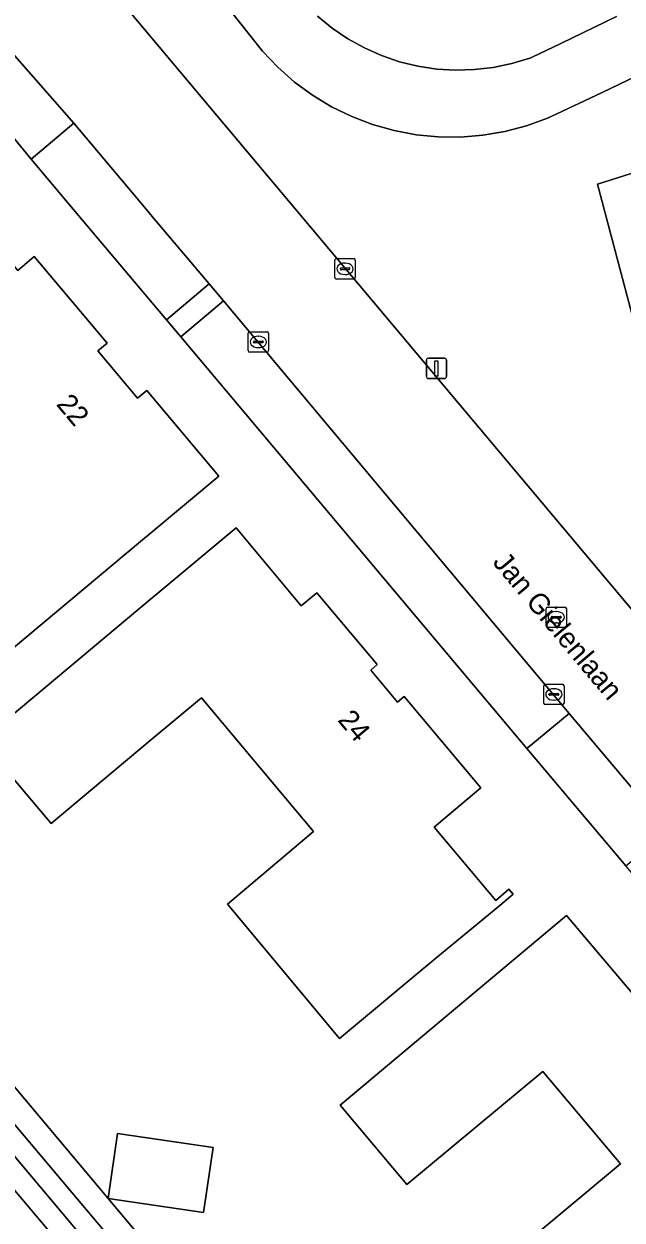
# Model space of a CAD drawing. Extents: x 157320 to 158835, y 386650 to 388491.
# Drawn here: x 157993.7 to 158023.1, y 386950.3 to 387009.1 of the extents above; entities that cross this region are included whole.
import ezdxf

# ---------------------------------------------------------------- set-up
doc = ezdxf.new("R2010")
doc.units = 0
for name, color, linetype in [('IMGEO_Erf', 7, 'Continuous'), ('IMGEO_Fietspad_gesloten', 7, 'Continuous'), ('IMGEO_Groenvoorziening', 7, 'Continuous'), ('IMGEO_Kolk', 7, 'Continuous'), ('IMGEO_Lichtmast', 7, 'Continuous'), ('IMGEO_Oever', 7, 'Continuous'), ('IMGEO_Openbare_ruimte_label', 7, 'Continuous'), ('IMGEO_Pand', 7, 'Continuous'), ('IMGEO_Pand_nummerreeks', 7, 'Continuous'), ('IMGEO_Rijbaan_lokaal_gesloten', 7, 'Continuous'), ('IMGEO_Rioolput', 7, 'Continuous'), ('IMGEO_Voetpad_gesloten', 7, 'Continuous'), ('IMGEO_Voetpad_open', 7, 'Continuous'), ('IMGEO_Waterloop', 7, 'Continuous')]:
    doc.layers.add(name, color=color, linetype=linetype)

msp = doc.modelspace()

# ---------------------------------------------------------------- linework, layer by layer
at = {"layer": 'IMGEO_Erf'}
for points in [[(158061.764, 386921.937), (158049.754, 386936.46), (158049.074, 386937.309), (158043.836, 386943.4), (158043.806, 386943.933), (158041.197, 386947.04), (158040.654, 386947.173), (158036.643, 386951.87), (158036.592, 386951.93), (158036.351, 386951.727), (158033.168, 386955.508), (158033.423, 386955.739), (158033.372, 386955.799), (158023.244, 386967.75), (158018.379, 386973.505), (158001.394, 386993.731), (158000.702, 386994.555), (157996.119, 387000), (157994.061, 387002.445), (157991.12, 387006.005), (157981.864, 387017.312)], [(157951.635, 387006.472), (157997.832, 386951.408), (158016.34, 386929.351), (158048.856, 386891.347)], [(157990.995, 386999.823), (157993.395, 386996.984), (157994.208, 386997.671), (157997.781, 386993.415), (157997.322, 386993.03), (157999.27, 386990.709), (157999.729, 386991.094), (158000, 386990.771), (158003.264, 386986.881), (158000, 386984.153), (157999.428, 386983.675), (157989.657, 386975.511), (157984.94, 386981.114), (157989.74, 386985.139), (157988.369, 386986.825)], [(157992.925, 386974.986), (158000, 386980.903), (158000.279, 386981.136), (158004.114, 386984.343), (158007.316, 386980.509), (158008.084, 386981.151), (158011.045, 386977.626), (158010.724, 386977.356), (158012.042, 386975.786), (158012.363, 386976.056), (158016.124, 386971.575), (158014.48, 386970.19), (158013.83, 386969.643), (158016.858, 386966.049), (158017.508, 386966.596), (158017.714, 386966.351), (158017.064, 386965.804), (158013.926, 386963.212), (158009.198, 386959.269), (158003.685, 386965.861), (158007.917, 386969.425), (158002.409, 386976), (158000, 386973.982), (157996.362, 386970.934), (157995.044, 386969.83), (157991.606, 386973.883)]]:
    msp.add_lwpolyline(points, dxfattribs=at)
for points in [[(158016.504, 386962.101), (158020.335, 386965.313), (158024.467, 386960.406), (158025.064, 386960.909), (158028.925, 386956.316), (158028.489, 386955.95), (158029.563, 386954.671), (158029.999, 386955.037), (158030.996, 386953.85), (158028.685, 386951.9), (158031.502, 386948.56), (158027.669, 386945.35), (158021.051, 386939.806), (158015.277, 386946.677), (158022.978, 386953.106), (158019.17, 386957.649), (158012.501, 386952.091), (158009.217, 386955.992)], [(157997.832, 386951.408), (157998.299, 386954.602), (158002.985, 386953.918), (158002.518, 386950.723)]]:
    msp.add_lwpolyline(points, close=True, dxfattribs=at)
at = {"layer": 'IMGEO_Fietspad_gesloten'}
for points in [[(158000, 387014.593), (158004.726, 387008.62), (158005.406, 387007.76), (158006.16, 387006.964), (158006.983, 387006.238), (158007.867, 387005.589), (158008.805, 387005.021), (158009.791, 387004.54), (158010.815, 387004.148), (158011.87, 387003.85), (158012.948, 387003.647), (158014.039, 387003.541), (158015.136, 387003.533), (158016.229, 387003.623), (158017.31, 387003.81), (158018.369, 387004.093), (158019.399, 387004.47), (158020.111, 387004.794), (158022.082, 387005.73), (158023.75, 387006.523), (158024.549, 387006.903), (158025.479, 387007.148), (158024.525, 387009.988)], [(158022.793, 387009.457), (158020.054, 387008.136), (158018.644, 387007.455), (158018.536, 387007.416), (158017.647, 387007.145), (158016.738, 387006.954), (158015.816, 387006.845), (158014.887, 387006.818), (158013.96, 387006.875), (158013.041, 387007.015), (158012.139, 387007.236), (158011.26, 387007.537), (158010.411, 387007.915), (158009.6, 387008.367), (158008.832, 387008.89), (158008.114, 387009.48)]]:
    msp.add_lwpolyline(points, dxfattribs=at)
at = {"layer": 'IMGEO_Groenvoorziening'}
for points in [[(157972.38, 387041.273), (158000, 387008.374), (158007.03, 387000), (158030.213, 386972.386), (158034.557, 386967.207)], [(157937.472, 387021.971), (157943.823, 387013.736), (157955.389, 387000), (158000, 386947.022), (158042.278, 386896.814)], [(158021.858, 387001.215), (158025.16, 387002.262), (158023.75, 387006.523), (158022.082, 387005.73), (158020.111, 387004.794), (158019.399, 387004.47), (158018.369, 387004.093), (158017.31, 387003.81), (158016.229, 387003.623), (158015.136, 387003.533), (158014.039, 387003.541), (158012.948, 387003.647), (158011.87, 387003.85), (158010.815, 387004.148), (158009.791, 387004.54), (158008.805, 387005.021), (158007.867, 387005.589), (158006.983, 387006.238), (158006.16, 387006.964), (158005.406, 387007.76), (158004.726, 387008.62), (158000, 387014.593)], [(158008.114, 387009.48), (158008.832, 387008.89), (158009.6, 387008.367), (158010.411, 387007.915), (158011.26, 387007.537), (158012.139, 387007.236), (158013.041, 387007.015), (158013.96, 387006.875), (158014.887, 387006.818), (158015.816, 387006.845), (158016.738, 387006.954), (158017.647, 387007.145), (158018.536, 387007.416), (158018.644, 387007.455), (158020.054, 387008.136), (158022.793, 387009.457)], [(158114.42, 386884.644), (158119.718, 386887.267), (158096.05, 386915.628), (158091.265, 386912.857), (158097.876, 386904.822), (158111.36, 386888.673), (158104.009, 386884.795), (158101.35, 386883.538), (158092.91, 386880.238), (158090.042, 386879.509), (158087.103, 386878.964), (158081.422, 386878.627), (158075.571, 386878.874), (158072.605, 386879.295), (158066.74, 386880.636), (158063.836, 386881.61), (158061.143, 386882.788), (158054.735, 386886.23), (158052.006, 386888.362), (158048.856, 386891.347), (158016.34, 386929.351), (157997.832, 386951.408), (157951.635, 387006.472)], [(158036.34, 386968.464), (158033.937, 386975.727), (158031.36, 386974.604), (158026.145, 386985.028), (158021.858, 387001.215)]]:
    msp.add_lwpolyline(points, dxfattribs=at)
for points in [[(158002.787, 386996.322), (158000, 386999.639), (157999.697, 387000), (157996.153, 387004.218), (157994.061, 387002.445), (157996.119, 387000), (158000.702, 386994.555)], [(158025.908, 387000), (158025.16, 387002.262), (158021.858, 387001.215), (158026.145, 386985.028), (158031.36, 386974.604), (158033.937, 386975.727)], [(158020.47, 386975.229), (158003.5, 386995.491), (158001.394, 386993.731), (158018.379, 386973.505)]]:
    msp.add_lwpolyline(points, close=True, dxfattribs=at)
at = {"layer": 'IMGEO_Kolk'}
for p, q in [((158009.036, 386997.564), (158009.888, 386997.564)), ((158008.961, 386996.638), (158008.961, 386997.49)), ((158009.22, 386997.058), (158009.22, 386997.07)), ((158009.658, 386997.021), (158009.26, 386997.021)), ((158009.263, 386997.107), (158009.661, 386997.107)), ((158009.449, 386997.344), (158009.474, 386997.344)), ((158009.704, 386997.07), (158009.704, 386997.058)), ((158009.962, 386997.49), (158009.962, 386996.638)), ((158009.888, 386996.564), (158009.036, 386996.564)), ((158009.472, 386996.784), (158009.447, 386996.784)), ((158004.706, 386993.048), (158004.706, 386993.9)), ((158004.781, 386993.974), (158005.633, 386993.974)), ((158004.965, 386993.468), (158004.965, 386993.48)), ((158005.008, 386993.517), (158005.406, 386993.517)), ((158005.194, 386993.754), (158005.219, 386993.754)), ((158005.449, 386993.48), (158005.449, 386993.468)), ((158005.707, 386993.9), (158005.707, 386993.048)), ((158005.633, 386992.974), (158004.781, 386992.974)), ((158005.403, 386993.431), (158005.005, 386993.431)), ((158005.217, 386993.194), (158005.192, 386993.194)), ((158019.213, 386975.737), (158019.213, 386976.589)), ((158019.288, 386976.663), (158020.14, 386976.663)), ((158019.701, 386976.443), (158019.726, 386976.443)), ((158020.214, 386976.589), (158020.214, 386975.737)), ((158019.472, 386976.157), (158019.472, 386976.169)), ((158019.91, 386976.12), (158019.512, 386976.12)), ((158019.515, 386976.206), (158019.913, 386976.206)), ((158019.724, 386975.883), (158019.699, 386975.883)), ((158019.956, 386976.169), (158019.956, 386976.157)), ((158020.14, 386975.663), (158019.288, 386975.663))]:
    msp.add_line(p, q, dxfattribs=at)
for points in [[(158009.036, 386997.564), (158009.888, 386997.564)], [(158008.961, 386996.638), (158008.961, 386997.49)], [(158009.962, 386997.49), (158009.962, 386996.638)], [(158009.888, 386996.564), (158009.036, 386996.564)], [(158004.706, 386993.048), (158004.706, 386993.9)], [(158004.781, 386993.974), (158005.633, 386993.974)], [(158005.707, 386993.9), (158005.707, 386993.048)], [(158005.633, 386992.974), (158004.781, 386992.974)], [(158019.213, 386975.737), (158019.213, 386976.589)], [(158019.288, 386976.663), (158020.14, 386976.663)], [(158020.214, 386976.589), (158020.214, 386975.737)], [(158020.14, 386975.663), (158019.288, 386975.663)]]:
    msp.add_lwpolyline(points, dxfattribs=at)
for centre, radius, start, end in [((158009.038, 386997.488), 0.0765, 91.55205, 178.44795), ((158009.038, 386997.488), 0.0765, 91.55205, 178.44795), ((158009.886, 386997.488), 0.0765, 1.55205, 88.44795), ((158009.886, 386997.488), 0.0765, 1.55205, 88.44795), ((158009.26, 386997.067), 0.0403, 85.87752, 175.75265), ((158009.257, 386997.057), 0.0366, 178.93798, 274.71019), ((158009.661, 386997.064), 0.043, 264.86636, 352.45326), ((158009.665, 386997.069), 0.0386, 1.73085, 96.63898), ((158009.038, 386996.64), 0.0765, 181.55205, 268.44795), ((158009.038, 386996.64), 0.0765, 181.55205, 268.44795), ((158009.886, 386996.64), 0.0765, 271.55205, 358.44795), ((158009.886, 386996.64), 0.0765, 271.55205, 358.44795), ((158004.783, 386993.898), 0.0765, 91.55205, 178.44795), ((158004.783, 386993.898), 0.0765, 91.55205, 178.44795), ((158005.005, 386993.477), 0.0403, 85.87752, 175.75265), ((158005.002, 386993.467), 0.0366, 178.93798, 274.71019), ((158005.406, 386993.474), 0.043, 264.86636, 352.45326), ((158005.41, 386993.479), 0.0386, 1.73085, 96.63898), ((158005.631, 386993.898), 0.0765, 1.55205, 88.44795), ((158005.631, 386993.898), 0.0765, 1.55205, 88.44795), ((158004.783, 386993.05), 0.0765, 181.55205, 268.44795), ((158004.783, 386993.05), 0.0765, 181.55205, 268.44795), ((158005.631, 386993.05), 0.0765, 271.55205, 358.44795), ((158005.631, 386993.05), 0.0765, 271.55205, 358.44795), ((158019.29, 386976.587), 0.0765, 91.55205, 178.44795), ((158019.29, 386976.587), 0.0765, 91.55205, 178.44795), ((158020.138, 386976.587), 0.0765, 1.55205, 88.44795), ((158020.138, 386976.587), 0.0765, 1.55205, 88.44795), ((158019.512, 386976.166), 0.0403, 85.87752, 175.75265), ((158019.509, 386976.156), 0.0366, 178.93798, 274.71019), ((158019.913, 386976.163), 0.043, 264.86636, 352.45326), ((158019.917, 386976.168), 0.0386, 1.73085, 96.63898), ((158019.29, 386975.739), 0.0765, 181.55205, 268.44795), ((158019.29, 386975.739), 0.0765, 181.55205, 268.44795), ((158020.138, 386975.739), 0.0765, 271.55205, 358.44795), ((158020.138, 386975.739), 0.0765, 271.55205, 358.44795)]:
    msp.add_arc(centre, radius, start, end, dxfattribs=at)
for centre, major_axis, ratio, start_param, end_param in [((158009.448, 386997.064), (-0.387, 0.002), 0.722429, 4.712389, 7.853982), ((158009.473, 386997.064), (-0.39, 0.002), 0.717154, 1.570796, 4.712389), ((158005.193, 386993.474), (-0.387, 0.002), 0.722429, 4.712389, 7.853982), ((158005.218, 386993.474), (-0.39, 0.002), 0.717154, 1.570796, 4.712389), ((158019.7, 386976.163), (-0.387, 0.002), 0.722429, 4.712389, 7.853982), ((158019.725, 386976.163), (-0.39, 0.002), 0.717154, 1.570796, 4.712389)]:
    msp.add_ellipse(centre, major_axis=major_axis, ratio=ratio, start_param=start_param, end_param=end_param, dxfattribs=at)
at = {"layer": 'IMGEO_Lichtmast'}
for p, q in [((158013.454, 386991.775), (158013.454, 386992.575)), ((158013.454, 386992.575), (158013.454, 386991.775)), ((158013.554, 386992.675), (158014.344, 386992.675)), ((158014.344, 386992.675), (158013.554, 386992.675)), ((158014.444, 386992.575), (158014.444, 386991.775)), ((158014.444, 386991.775), (158014.444, 386992.575)), ((158014.344, 386991.675), (158013.554, 386991.675)), ((158013.554, 386991.675), (158014.344, 386991.675))]:
    msp.add_line(p, q, dxfattribs=at)
msp.add_lwpolyline([(158013.874, 386992.55), (158014.024, 386992.55), (158014.024, 386991.8), (158013.874, 386991.8), (158013.874, 386992.55)], dxfattribs=at)
for centre, start, end in [((158013.554, 386992.575), 90, 180), ((158013.554, 386992.575), 90, 180), ((158014.344, 386992.575), 0, 90), ((158014.344, 386992.575), 360, 90), ((158013.554, 386991.775), 180, 270), ((158013.554, 386991.775), 180, 270), ((158014.344, 386991.775), 270, 0), ((158014.344, 386991.775), 270, 0)]:
    msp.add_arc(centre, 0.1, start, end, dxfattribs=at)
at = {"layer": 'IMGEO_Oever'}
for points in [[(158042.278, 386896.814), (158000, 386947.022), (157955.389, 387000), (157943.823, 387013.736), (157937.472, 387021.971)], [(158035.782, 386900.577), (157998.707, 386945.337), (157938.923, 387016.244)], [(157951.031, 387003.711), (158044.337, 386892.64)]]:
    msp.add_lwpolyline(points, dxfattribs=at)
at = {"layer": 'IMGEO_Pand'}
for points in [[(157988.369, 386986.825), (157989.74, 386985.139), (157984.94, 386981.114), (157989.657, 386975.511), (157999.428, 386983.675), (158000, 386984.153), (158003.264, 386986.881), (158000, 386990.771), (157999.729, 386991.094), (157999.27, 386990.709), (157997.322, 386993.03), (157997.781, 386993.415), (157994.208, 386997.671), (157993.395, 386996.984), (157990.995, 386999.823), (157987.378, 386996.792), (157987.163, 386996.612), (157983.045, 386993.162), (157984.645, 386991.256)], [(157991.606, 386973.883), (157995.044, 386969.83), (157996.362, 386970.934), (158000, 386973.982), (158002.409, 386976), (158007.917, 386969.425), (158003.685, 386965.861), (158009.198, 386959.269), (158013.926, 386963.212), (158017.064, 386965.804), (158017.714, 386966.351), (158017.508, 386966.596), (158016.858, 386966.049), (158013.83, 386969.643), (158014.48, 386970.19), (158016.124, 386971.575), (158012.363, 386976.056), (158012.042, 386975.786), (158010.724, 386977.356), (158011.045, 386977.626), (158008.084, 386981.151), (158007.316, 386980.509), (158004.114, 386984.343), (158000.279, 386981.136), (158000, 386980.903), (157992.925, 386974.986)]]:
    msp.add_lwpolyline(points, dxfattribs=at)
for points in [[(158029.999, 386955.037), (158029.563, 386954.671), (158028.489, 386955.95), (158028.925, 386956.316), (158025.064, 386960.909), (158024.467, 386960.406), (158020.335, 386965.313), (158016.504, 386962.101), (158009.217, 386955.992), (158012.501, 386952.091), (158019.17, 386957.649), (158022.978, 386953.106), (158015.277, 386946.677), (158021.051, 386939.806), (158027.669, 386945.35), (158031.502, 386948.56), (158028.685, 386951.9), (158030.996, 386953.85)], [(157997.832, 386951.408), (158002.518, 386950.723), (158002.985, 386953.918), (157998.299, 386954.602)]]:
    msp.add_lwpolyline(points, close=True, dxfattribs=at)
at = {"layer": 'IMGEO_Rijbaan_lokaal_gesloten'}
for points in [[(158073.076, 386921.282), (158041.42, 386959.024), (158034.557, 386967.207), (158030.213, 386972.386), (158007.03, 387000), (158000, 387008.374), (157972.38, 387041.273)], [(157967.973, 387037.769), (157974.9, 387029.543), (157977.042, 387026.998), (157978.062, 387025.786), (157980.721, 387022.628), (157983.795, 387018.928), (157993.128, 387007.669), (157996.153, 387004.218), (157999.697, 387000), (158000, 386999.639), (158002.787, 386996.322), (158003.5, 386995.491), (158020.47, 386975.229), (158025.301, 386969.475), (158035.357, 386957.488), (158038.597, 386953.625), (158042.903, 386948.477), (158045.801, 386945.052), (158050.997, 386938.872), (158051.663, 386938.08), (158063.817, 386923.608), (158065.16, 386922.009), (158067.446, 386919.287)]]:
    msp.add_lwpolyline(points, dxfattribs=at)
at = {"layer": 'IMGEO_Rioolput'}
for p, q in [((158019.328, 386979.527), (158019.328, 386980.379)), ((158019.403, 386980.453), (158020.255, 386980.453)), ((158019.587, 386979.947), (158019.587, 386979.959)), ((158019.63, 386979.996), (158020.028, 386979.996)), ((158019.816, 386980.233), (158019.841, 386980.233)), ((158020.071, 386979.959), (158020.071, 386979.947)), ((158020.329, 386980.379), (158020.329, 386979.527)), ((158020.255, 386979.453), (158019.403, 386979.453)), ((158020.025, 386979.91), (158019.627, 386979.91)), ((158019.839, 386979.673), (158019.814, 386979.673))]:
    msp.add_line(p, q, dxfattribs=at)
for points in [[(158019.328, 386979.527), (158019.328, 386980.379)], [(158019.403, 386980.453), (158020.255, 386980.453)], [(158020.329, 386980.379), (158020.329, 386979.527)], [(158020.255, 386979.453), (158019.403, 386979.453)]]:
    msp.add_lwpolyline(points, dxfattribs=at)
for centre, radius, start, end in [((158019.405, 386980.377), 0.0765, 91.55205, 178.44795), ((158019.405, 386980.377), 0.0765, 91.55205, 178.44795), ((158019.627, 386979.956), 0.0403, 85.87752, 175.75265), ((158019.624, 386979.946), 0.0366, 178.93798, 274.71019), ((158020.028, 386979.953), 0.043, 264.86636, 352.45326), ((158020.032, 386979.958), 0.0386, 1.73085, 96.63898), ((158020.253, 386980.377), 0.0765, 1.55205, 88.44795), ((158020.253, 386980.377), 0.0765, 1.55205, 88.44795), ((158019.405, 386979.529), 0.0765, 181.55205, 268.44795), ((158019.405, 386979.529), 0.0765, 181.55205, 268.44795), ((158020.253, 386979.529), 0.0765, 271.55205, 358.44795), ((158020.253, 386979.529), 0.0765, 271.55205, 358.44795)]:
    msp.add_arc(centre, radius, start, end, dxfattribs=at)
for centre, major_axis, ratio, start_param, end_param in [((158019.815, 386979.953), (-0.387, 0.002), 0.722429, 4.712389, 7.853982), ((158019.84, 386979.953), (-0.39, 0.002), 0.717154, 1.570796, 4.712389)]:
    msp.add_ellipse(centre, major_axis=major_axis, ratio=ratio, start_param=start_param, end_param=end_param, dxfattribs=at)
at = {"layer": 'IMGEO_Voetpad_gesloten'}
msp.add_lwpolyline([(158020.47, 386975.229), (158018.379, 386973.505), (158023.244, 386967.75), (158025.301, 386969.475)], close=True, dxfattribs=at)
at = {"layer": 'IMGEO_Voetpad_open'}
for points in [[(157993.128, 387007.669), (157991.12, 387006.005), (157994.061, 387002.445), (157996.153, 387004.218)], [(158001.394, 386993.731), (158003.5, 386995.491), (158002.787, 386996.322), (158000.702, 386994.555)]]:
    msp.add_lwpolyline(points, close=True, dxfattribs=at)
at = {"layer": 'IMGEO_Waterloop'}
for points in [[(157938.923, 387016.244), (157998.707, 386945.337), (158035.782, 386900.577)], [(158044.337, 386892.64), (157951.031, 387003.711)]]:
    msp.add_lwpolyline(points, dxfattribs=at)

# ---------------------------------------------------------------- texts
at = {"layer": 'IMGEO_Openbare_ruimte_label'}
msp.add_text('Jan Gielenlaan', height=1, rotation=310.01096, dxfattribs=at).set_placement((158016.668, 386982.633))
at = {"layer": 'IMGEO_Pand_nummerreeks'}
for s, rotation, p in [('22', 310.0037, (157995.251, 386990.396)), ('24', 310.01516, (158009.061, 386974.887))]:
    msp.add_text(s, height=1, rotation=rotation, dxfattribs=at).set_placement(p)

doc.saveas('drawing.dxf')
